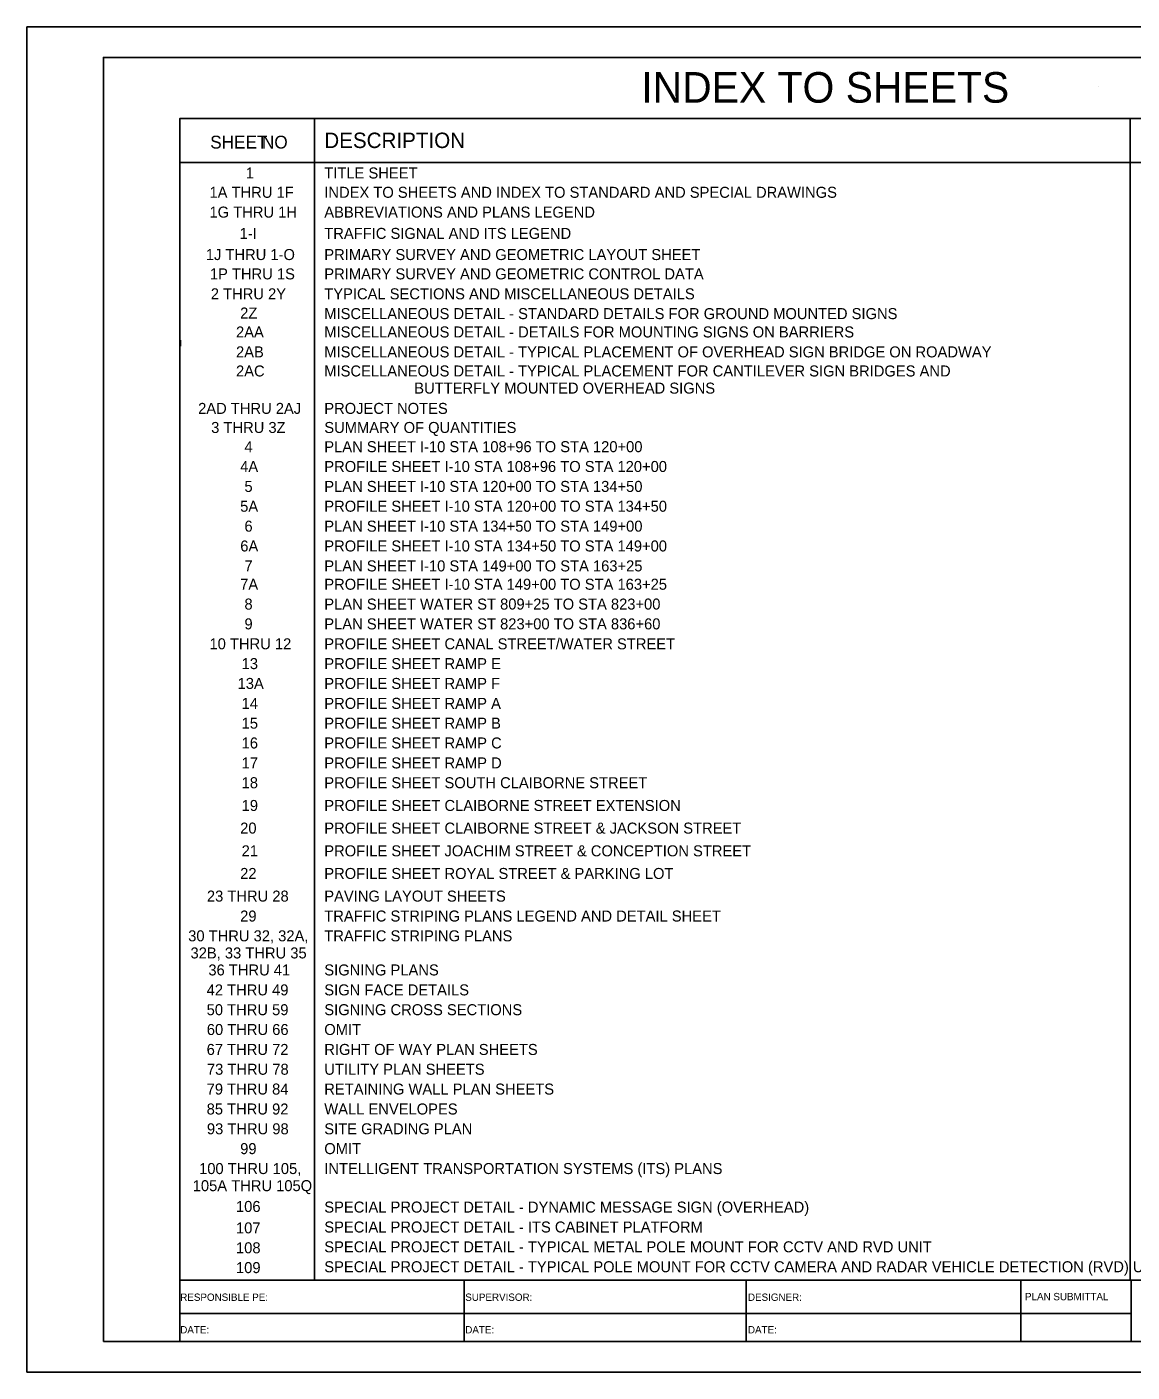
# Model space of a CAD drawing. Extents: x -12822 to 16384, y -6351 to 1913.
# Drawn here: x -850 to 54, y 782 to 1882 of the extents above; entities that cross this region are included whole.
import ezdxf

# ---------------------------------------------------------------- set-up
doc = ezdxf.new("R2010")
doc.units = 0
for name, color, linetype in [('2', 7, 'Continuous'), ('ANNO-SHT', 7, 'Continuous'), ('ANNO-TXT', 7, 'Continuous'), ('AXIS', 7, 'Continuous'), ('DRAINAGE', 7, 'Continuous'), ('Level 1', 7, 'Continuous'), ('Level 10', 7, 'Continuous'), ('Level 62', 7, 'Continuous'), ('SHT-BDR', 7, 'Continuous'), ('SHT-BNDRY', 7, 'Continuous')]:
    doc.layers.add(name, color=color, linetype=linetype)

# ---------------------------------------------------------------- blocks, each defined once
blk = doc.blocks.new('SC47208')
at = {"layer": 'Level 1'}
blk.add_line((0, 0), (0, 0), dxfattribs=at)

msp = doc.modelspace()

# ---------------------------------------------------------------- linework, layer by layer
at = {"layer": '2'}
msp.add_lwpolyline([(-724.5, 1626.2), (-724.5, 1621.2)], dxfattribs=at)
msp.add_lwpolyline([(-724.5, 1626.2), (-724.5, 1621.2)], dxfattribs=at)
at = {"layer": 'AXIS'}
msp.add_line((-725, 1407.3), (-725, 1407.3), dxfattribs=at)
at = {"layer": 'Level 1'}
for p, q in [((-614.7, 857.3), (-614.7, 1807.3)), ((52.2, 857.3), (52.2, 1807.3)), ((-725, 1771.3), (775, 1771.3))]:
    msp.add_line(p, q, dxfattribs=at)
at = {"layer": 'Level 62'}
msp.add_lwpolyline([(-850, 782.3), (850, 782.3), (850, 1882.3), (-850, 1882.3)], close=True, dxfattribs=at)
at = {"layer": 'SHT-BDR'}
msp.add_lwpolyline([(-725, 857.3), (775, 857.3), (775, 1807.3), (-725, 1807.3)], close=True, dxfattribs=at)
at = {"layer": 'SHT-BNDRY'}
for p, q in [((-725, 807.3), (-725, 857.3)), ((-492.4, 857.3), (-492.4, 807.3)), ((-261.7, 807.3), (-261.7, 857.3)), ((-37.1, 807.3), (-37.1, 857.3)), ((53.1, 807.3), (53.1, 857.3)), ((-725, 830.3), (53.1, 830.3))]:
    msp.add_line(p, q, dxfattribs=at)
msp.add_lwpolyline([(-787.5, 807.3), (825, 807.3), (825, 1857.3), (-787.5, 1857.3)], close=True, dxfattribs=at)

# ---------------------------------------------------------------- block references
at = {"layer": 'DRAINAGE', "rotation": -116.41666666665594}
msp.add_blockref('SC47208', (26.6, 1833.2), dxfattribs=at)
msp.add_blockref('SC47208', (26.6, 1833.2), dxfattribs=at)

# ---------------------------------------------------------------- texts
at = {"layer": 'ANNO-SHT'}
msp.add_text('            INDEX TO SHEETS            ', height=24.998, dxfattribs=at).set_placement((-459, 1820.3))
at = {"layer": 'ANNO-TXT'}
for s, p in [('PLAN SUBMITTAL', (-33.7, 841)), ('RESPONSIBLE PE:', (-724.6, 840.5)), ('SUPERVISOR:', (-491.5, 840.5)), ('DESIGNER:', (-260.3, 840.5)), ('DATE:', (-724.6, 813.9)), ('DATE:', (-491.5, 813.9)), ('DATE:', (-260.3, 813.9))]:
    msp.add_text(s, height=6, rotation=360, dxfattribs=at).set_placement(p)
at = {"layer": 'Level 10'}
for s, height, p in [('SHEET', 10.5, (-700.1, 1782.8)), (' NO', 10.5, (-661.7, 1782.8)), ('DESCRIPTION', 12.6, (-606.8, 1783.2)), ('1', 9, (-671, 1758.3)), ('TITLE SHEET', 9, (-606.8, 1758.3)), ('1A THRU 1F', 9, (-700.7, 1742.5)), ('INDEX TO SHEETS AND INDEX TO STANDARD AND SPECIAL DRAWINGS', 9, (-606.8, 1742.5)), ('1G THRU 1H', 9, (-700.7, 1726.3)), ('ABBREVIATIONS AND PLANS LEGEND', 9, (-606.8, 1726.3)), ('1-I', 9, (-676, 1708.9)), ('TRAFFIC SIGNAL AND ITS LEGEND', 9, (-606.8, 1708.9)), ('1J THRU 1-O', 9, (-703.7, 1691.6)), ('PRIMARY SURVEY AND GEOMETRIC LAYOUT SHEET', 9, (-606.8, 1691.6)), ('1P THRU 1S', 9, (-700.4, 1675.8)), ('PRIMARY SURVEY AND GEOMETRIC CONTROL DATA', 9, (-606.8, 1675.8)), ('2 THRU 2Y', 9, (-699.6, 1659.5)), ('TYPICAL SECTIONS AND MISCELLANEOUS DETAILS', 9, (-606.8, 1659.5)), ('2Z', 9, (-675.6, 1643.8)), ('MISCELLANEOUS DETAIL - STANDARD DETAILS FOR GROUND MOUNTED SIGNS', 9, (-606.8, 1643.3)), ('2AA', 9, (-679, 1628.3)), ('MISCELLANEOUS DETAIL - DETAILS FOR MOUNTING SIGNS ON BARRIERS', 9, (-606.8, 1628.3)), ('2AB', 9, (-679, 1612)), ('MISCELLANEOUS DETAIL - TYPICAL PLACEMENT OF OVERHEAD SIGN BRIDGE ON ROADWAY', 9, (-606.8, 1612)), ('2AC', 9, (-679, 1596.4)), ('MISCELLANEOUS DETAIL - TYPICAL PLACEMENT FOR CANTILEVER SIGN BRIDGES AND', 9, (-606.8, 1596.4)), ('                      BUTTERFLY MOUNTED OVERHEAD SIGNS', 9, (-606.8, 1582.4)), ('2AD THRU 2AJ', 9, (-710, 1565.8)), ('PROJECT NOTES', 9, (-606.8, 1565.8)), ('3 THRU 3Z', 9, (-699.3, 1550.2)), ('SUMMARY OF QUANTITIES ', 9, (-606.8, 1550.2)), ('4', 9, (-672.1, 1534.5)), ('PLAN SHEET I-10 STA 108+96 TO STA 120+00', 9, (-606.8, 1534.5)), ('4A', 9, (-675.6, 1518.3)), ('PROFILE SHEET I-10 STA 108+96 TO STA 120+00', 9, (-606.8, 1518.3)), ('5', 9, (-672.1, 1502)), ('PLAN SHEET I-10 STA 120+00 TO STA 134+50', 9, (-606.8, 1502)), ('5A', 9, (-675.6, 1485.8)), ('PROFILE SHEET I-10 STA 120+00 TO STA 134+50', 9, (-606.8, 1485.8)), ('6', 9, (-672.1, 1469.5)), ('PLAN SHEET I-10 STA 134+50 TO STA 149+00', 9, (-606.8, 1469.5)), ('6A', 9, (-675.5, 1453.3)), ('PROFILE SHEET I-10 STA 134+50 TO STA 149+00', 9, (-606.8, 1453.3)), ('7', 9, (-672.1, 1437)), ('PLAN SHEET I-10 STA 149+00 TO STA 163+25', 9, (-606.8, 1437)), ('7A', 9, (-675.6, 1422)), ('PROFILE SHEET I-10 STA 149+00 TO STA 163+25', 9, (-606.8, 1422)), ('8', 9, (-672.1, 1405.8)), ('PLAN SHEET WATER ST 809+25 TO STA 823+00', 9, (-606.8, 1405.8)), ('9', 9, (-672.1, 1389.6)), ('PLAN SHEET WATER ST 823+00 TO STA 836+60', 9, (-606.8, 1389.6)), ('10 THRU 12', 9, (-700.7, 1373.3)), ('PROFILE SHEET CANAL STREET/WATER STREET', 9, (-606.8, 1373.3)), ('13', 9, (-674.4, 1357.1)), ('PROFILE SHEET RAMP E', 9, (-606.8, 1357.1)), ('13A', 9, (-677.7, 1340.9)), ('PROFILE SHEET RAMP F', 9, (-606.8, 1340.9)), ('14', 9, (-674.4, 1324.6)), ('PROFILE SHEET RAMP A', 9, (-606.8, 1324.6)), ('15', 9, (-674.4, 1308.4)), ('PROFILE SHEET RAMP B', 9, (-606.8, 1308.4)), ('16', 9, (-674.4, 1292.2)), ('PROFILE SHEET RAMP C', 9, (-606.8, 1292.2)), ('17', 9, (-674.4, 1275.9)), ('PROFILE SHEET RAMP D', 9, (-606.8, 1275.9)), ('18', 9, (-674.4, 1259.7)), ('PROFILE SHEET SOUTH CLAIBORNE STREET', 9, (-606.8, 1259.7)), ('19', 9, (-674.4, 1241.1)), ('PROFILE SHEET CLAIBORNE STREET EXTENSION', 9, (-606.8, 1241.1)), ('20', 9, (-675.6, 1222.6)), ('PROFILE SHEET CLAIBORNE STREET & JACKSON STREET', 9, (-606.8, 1222.6)), ('21', 9, (-674.4, 1204)), ('PROFILE SHEET JOACHIM STREET & CONCEPTION STREET', 9, (-606.8, 1204)), ('22', 9, (-675.6, 1185.5)), ('PROFILE SHEET ROYAL STREET & PARKING LOT', 9, (-606.8, 1185.5)), ('23 THRU 28', 9, (-702.8, 1167)), ('PAVING LAYOUT SHEETS', 9, (-606.8, 1167)), ('29', 9, (-675.6, 1150.7)), ('TRAFFIC STRIPING PLANS LEGEND AND DETAIL SHEET', 9, (-606.8, 1150.7)), ('30 THRU 32, 32A,', 9, (-718.1, 1134.5)), ('TRAFFIC STRIPING PLANS', 9, (-606.8, 1134.5)), ('32B, 33 THRU 35', 9, (-716.2, 1120.5)), ('36 THRU 41', 9, (-701.6, 1106.6)), ('SIGNING PLANS', 9, (-606.8, 1106.6)), ('42 THRU 49', 9, (-703, 1090.3)), ('SIGN FACE DETAILS', 9, (-606.8, 1090.3)), ('50 THRU 59', 9, (-703, 1074.1)), ('SIGNING CROSS SECTIONS', 9, (-606.8, 1074.1)), ('60 THRU 66', 9, (-702.9, 1057.9)), ('OMIT', 9, (-606.8, 1057.9)), ('67 THRU 72', 9, (-703, 1041.6)), ('RIGHT OF WAY PLAN SHEETS', 9, (-606.8, 1041.6)), ('73 THRU 78', 9, (-702.8, 1025.4)), ('UTILITY PLAN SHEETS', 9, (-606.8, 1025.4)), ('79 THRU 84', 9, (-703, 1009.2)), ('RETAINING WALL PLAN SHEETS', 9, (-606.8, 1009.2)), ('85 THRU 92', 9, (-703, 992.9)), ('WALL ENVELOPES', 9, (-606.8, 992.9)), ('93 THRU 98', 9, (-702.8, 976.7)), ('SITE GRADING PLAN', 9, (-606.8, 976.7)), ('99', 9, (-675.6, 960.5)), ('OMIT', 9, (-606.8, 960.5)), ('100 THRU 105,', 9, (-709.2, 944.2)), ('INTELLIGENT TRANSPORTATION SYSTEMS (ITS) PLANS', 9, (-606.8, 944.2)), ('105A THRU 105Q', 9, (-714.4, 930.2)), ('106', 9, (-679, 913.2)), ('SPECIAL PROJECT DETAIL - DYNAMIC MESSAGE SIGN (OVERHEAD)', 9, (-606.8, 912.7)), ('107', 9, (-679, 895.7)), ('SPECIAL PROJECT DETAIL - ITS CABINET PLATFORM', 9, (-606.8, 896.4)), ('108', 9, (-679, 879.4)), ('SPECIAL PROJECT DETAIL - TYPICAL METAL POLE MOUNT FOR CCTV AND RVD UNIT', 9, (-606.8, 880.2)), ('109', 9, (-679, 863.2)), ('SPECIAL PROJECT DETAIL - TYPICAL POLE MOUNT FOR CCTV CAMERA AND RADAR VEHICLE DETECTION (RVD) UNIT', 9, (-606.8, 863.9))]:
    msp.add_text(s, height=height, dxfattribs=at).set_placement(p)

doc.saveas('drawing.dxf')
